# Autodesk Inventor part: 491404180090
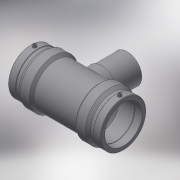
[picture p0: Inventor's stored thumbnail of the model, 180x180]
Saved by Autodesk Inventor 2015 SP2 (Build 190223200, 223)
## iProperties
Created: 2017-06
Part Number: 491404180090
Material: Generic
Description: PLASSON REDUCING TEE 180x90x180
Document SubType Name: Modeling
Designer: KIM
Mass: 7604.42 g
Surface Area: 6248.08 cm^2
Volume: 7604.42 cm^3
Density: 1 g/cm^3
Appearance: Default
Author: KIM
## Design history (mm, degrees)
derived "491404.ipt"
feature "Solid1::491404.ipt"
tag "TaggingFeature1"
body "Solid1"
other parameters: "d0" = 422, "d2" = 245, "d3" = 106, "d4" = 84.4, "d5" = 220.5, "d6" = 171, "d8" = 168 deg, "d10" = 42.4, "d11" = 14.13333, "d13" = 422, "d14" = 17.6296, "d17" = 162, "d19" = 3.52592, "d20" = 168 deg, "d22" = 227.85, "d23" = 245, "d25" = 135 deg, "d26" = 295.4, "d29" = 116, "d30" = 15, "d31" = 168.8, "d34" = 5 deg, "d35" = 15, "d39" = 5 deg, "d41" = 4, "d42" = 14, "d43" = 0, "d45" = 4, "d46" = 6, "d47" = 0, "d51" = 0, "d52" = 72, "d54" = 0, "d55" = 220.5, "d56" = 245, "d57" = 147.7, "d58" = 135 deg, "d59" = 106, "d60" = 106, "d61" = 135 deg, "d72" = 192.01, "d73" = 96.005, "d75" = 94.5, "d77" = 0, "d78" = 72, "d80" = 0, "d82" = 77.5, "d83" = 0, "d84" = 3, "d85" = 0, "d86" = 35.33333, "d87" = 223.293, "d88" = 14.13333, "d89" = 3, "d90" = 0, "L_" = 422, "L_1" = 106, "D_" = 245, "A_" = 116, "d_2" = 12
